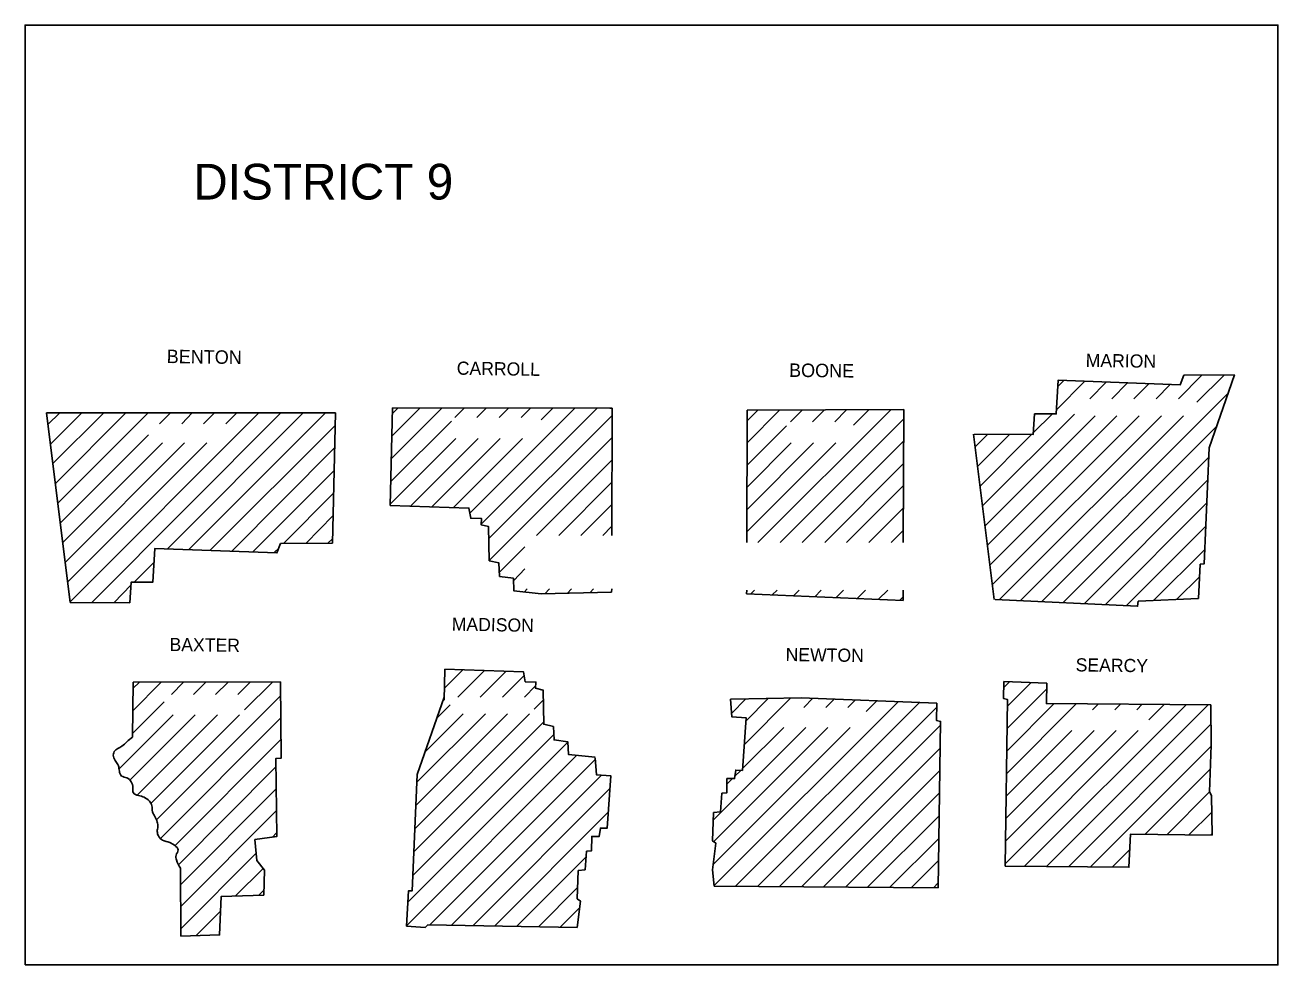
# Model space of a CAD drawing. Extents: x 76 to 6945, y -3933 to 2152.
# Drawn here: x 6134.1 to 6534.1, y -3562.5 to -3262.5 of the extents above; entities that cross this region are included whole.
import ezdxf

# ---------------------------------------------------------------- set-up
doc = ezdxf.new("R2010")
doc.units = 0
doc.layers.add('R_Draft', color=7, linetype='Continuous')

msp = doc.modelspace()

# ---------------------------------------------------------------- linework, layer by layer
at = {"layer": 'R_Draft'}
msp.add_lwpolyline([(6134.06, -3562.46), (6134.06, -3262.46), (6534.06, -3262.46), (6534.06, -3562.46)], close=True, dxfattribs=at)
for points in [[(6437.16, -3393.06), (6455.86, -3393.16), (6456.36, -3386.56), (6463.26, -3386.56), (6463.86, -3375.86), (6502.86, -3377.26), (6504.06, -3374.26), (6520.16, -3374.16), (6512.06, -3397.36), (6510.46, -3434.46), (6509.26, -3434.56), (6508.66, -3445.46)], [(6463.76, -3377.86), (6465.66, -3375.96)], [(6502.26, -3381.76), (6509.76, -3374.26)], [(6508.16, -3382.86), (6516.86, -3374.26)], [(6463.36, -3385.26), (6472.36, -3376.16)], [(6473.96, -3381.76), (6479.26, -3376.46)], [(6481.06, -3381.76), (6486.06, -3376.66)], [(6488.06, -3381.76), (6492.96, -3376.86)], [(6495.16, -3381.76), (6499.66, -3377.16)], [(6451.86, -3446.16), (6518.06, -3380.06)], [(6148.46, -3446.76), (6140.86, -3386.26)], [(6140.86, -3386.26), (6233.16, -3386.26)], [(6141.36, -3389.96), (6145.16, -3386.26)], [(6142.16, -3396.26), (6152.16, -3386.26)], [(6142.96, -3402.46), (6159.16, -3386.26)], [(6143.76, -3408.76), (6166.26, -3386.26)], [(6144.56, -3415.06), (6173.36, -3386.26)], [(6148.56, -3446.46), (6208.66, -3386.26)], [(6155.36, -3446.76), (6215.76, -3386.26)], [(6176.96, -3389.76), (6180.46, -3386.26)], [(6179.46, -3429.76), (6222.86, -3386.26)], [(6184.06, -3389.76), (6187.46, -3386.26)], [(6186.26, -3429.96), (6229.96, -3386.26)], [(6191.06, -3389.76), (6194.56, -3386.26)], [(6198.16, -3389.76), (6201.66, -3386.26)], [(6233.16, -3386.26), (6232.26, -3427.86)], [(6250.66, -3415.86), (6251.36, -3384.66)], [(6250.96, -3400.96), (6267.26, -3384.66)], [(6251.16, -3393.66), (6260.16, -3384.66)], [(6251.36, -3386.46), (6253.16, -3384.66)], [(6251.36, -3384.66), (6320.76, -3384.76), (6321.46, -3384.76)], [(6271.26, -3387.76), (6274.36, -3384.66)], [(6276.06, -3418.26), (6309.56, -3384.76)], [(6278.26, -3387.76), (6281.36, -3384.66)], [(6279.66, -3421.76), (6316.66, -3384.76)], [(6282.16, -3426.36), (6321.46, -3387.06)], [(6285.46, -3387.76), (6288.36, -3384.76)], [(6292.46, -3387.76), (6295.46, -3384.76)], [(6298.86, -3388.46), (6302.56, -3384.76)], [(6321.46, -3384.76), (6321.36, -3425.36)], [(6364.46, -3388.86), (6367.96, -3385.36)], [(6364.46, -3427.66), (6364.56, -3385.36)], [(6364.56, -3385.36), (6414.66, -3385.16)], [(6364.56, -3395.86), (6374.96, -3385.36)], [(6368.06, -3427.66), (6410.46, -3385.26)], [(6378.46, -3389.06), (6382.16, -3385.36)], [(6385.46, -3389.06), (6389.16, -3385.36)], [(6392.56, -3389.06), (6396.26, -3385.36)], [(6398.56, -3390.16), (6403.46, -3385.26)], [(6414.66, -3385.16), (6414.46, -3427.66)], [(6439.76, -3415.96), (6469.06, -3386.66)], [(6440.56, -3422.26), (6475.66, -3387.16)], [(6441.36, -3428.46), (6482.66, -3387.16)], [(6442.16, -3434.76), (6489.76, -3387.16)], [(6442.96, -3441.06), (6496.86, -3387.16)], [(6445.16, -3445.86), (6503.96, -3387.16)], [(6455.96, -3392.66), (6462.06, -3386.56)], [(6193.06, -3430.16), (6233.06, -3390.26)], [(6250.86, -3408.16), (6270.16, -3388.86)], [(6364.56, -3402.96), (6377.16, -3390.36)], [(6375.16, -3427.66), (6414.56, -3388.26)], [(6458.66, -3446.46), (6514.26, -3390.86)], [(6145.36, -3421.36), (6173.46, -3393.26)], [(6146.16, -3427.66), (6177.96, -3395.86)], [(6146.96, -3433.86), (6184.96, -3395.86)], [(6147.76, -3440.16), (6192.06, -3395.86)], [(6250.66, -3415.36), (6271.56, -3394.46)], [(6257.16, -3416.06), (6278.76, -3394.46)], [(6263.96, -3416.26), (6285.76, -3394.46)], [(6270.86, -3416.46), (6292.86, -3394.46)], [(6282.26, -3433.36), (6321.46, -3394.16)], [(6364.46, -3424.26), (6392.86, -3395.86)], [(6364.46, -3417.16), (6385.76, -3395.86)], [(6364.56, -3409.96), (6378.66, -3395.86)], [(6382.16, -3427.66), (6414.56, -3395.26)], [(6443.46, -3445.86), (6436.86, -3393.06)], [(6437.36, -3397.06), (6441.46, -3393.06)], [(6438.16, -3403.36), (6448.46, -3393.06)], [(6438.96, -3409.66), (6455.46, -3393.06)], [(6199.96, -3430.46), (6232.86, -3397.46)], [(6297.36, -3425.36), (6321.36, -3401.36)], [(6389.36, -3427.66), (6414.56, -3402.46)], [(6465.36, -3446.86), (6511.96, -3400.36)], [(6206.66, -3430.76), (6232.76, -3404.66)], [(6472.16, -3447.16), (6511.56, -3407.76)], [(6216.56, -3427.96), (6232.56, -3411.86)], [(6304.46, -3425.36), (6321.36, -3408.36)], [(6396.36, -3427.66), (6414.56, -3409.46)], [(6321.36, -3442.46), (6321.26, -3443.46), (6298.86, -3443.96), (6290.16, -3443.06), (6289.96, -3439.06), (6285.56, -3438.46), (6285.36, -3434.16), (6282.26, -3433.46), (6282.06, -3422.56), (6279.66, -3421.96), (6279.76, -3419.96), (6276.36, -3419.86), (6275.76, -3416.66), (6250.66, -3415.86)], [(6311.46, -3425.36), (6321.26, -3415.56)], [(6478.96, -3447.46), (6511.26, -3415.06)], [(6223.66, -3427.96), (6232.46, -3419.06)], [(6403.46, -3427.66), (6414.46, -3416.66)], [(6318.56, -3425.36), (6321.26, -3422.56)], [(6410.56, -3427.66), (6414.46, -3423.76)], [(6485.66, -3447.76), (6510.96, -3422.56)], [(6232.26, -3427.86), (6215.66, -3427.96), (6214.46, -3430.96), (6175.46, -3429.56), (6174.86, -3440.26), (6167.96, -3440.26), (6167.46, -3446.86), (6148.46, -3446.76)], [(6230.66, -3427.96), (6232.36, -3426.36)], [(6213.46, -3430.96), (6215.16, -3429.36)], [(6285.56, -3437.06), (6293.66, -3428.96)], [(6494.36, -3446.16), (6510.56, -3429.96)], [(6168.86, -3440.26), (6175.26, -3433.86)], [(6290.06, -3439.76), (6293.66, -3436.06)], [(6501.86, -3445.66), (6509.06, -3438.56)], [(6162.36, -3446.86), (6167.96, -3441.16)], [(6293.46, -3443.36), (6294.36, -3442.46)], [(6299.96, -3443.96), (6301.46, -3442.46)], [(6307.16, -3443.86), (6308.56, -3442.46)], [(6314.46, -3443.56), (6315.56, -3442.46)], [(6364.36, -3444.06), (6364.46, -3442.86)], [(6365.76, -3444.06), (6366.96, -3442.86)], [(6372.56, -3444.36), (6374.16, -3442.86)], [(6379.36, -3444.66), (6381.16, -3442.86)], [(6386.16, -3444.96), (6388.26, -3442.86)], [(6392.96, -3445.26), (6395.36, -3442.86)], [(6399.76, -3445.46), (6402.36, -3442.86)], [(6406.56, -3445.76), (6409.46, -3442.86)], [(6414.46, -3442.86), (6414.36, -3446.16)], [(6414.36, -3446.16), (6364.36, -3444.06)], [(6413.36, -3446.06), (6414.46, -3444.96)], [(6508.66, -3445.46), (6489.46, -3446.36), (6489.26, -3447.96), (6443.76, -3445.86)], [(6267.86, -3477.96), (6268.06, -3468.06)], [(6267.86, -3474.26), (6273.86, -3468.26)], [(6268.06, -3468.06), (6293.16, -3468.86), (6293.76, -3472.06), (6297.16, -3472.16), (6297.06, -3474.16), (6299.46, -3474.76), (6299.66, -3485.66), (6302.76, -3486.36), (6302.96, -3490.66), (6307.36, -3491.26), (6307.56, -3495.26), (6316.06, -3496.16)], [(6272.26, -3476.96), (6280.66, -3468.56)], [(6279.36, -3476.96), (6287.56, -3468.76)], [(6286.46, -3476.96), (6293.36, -3470.06)], [(6446.96, -3530.96), (6447.76, -3477.76), (6446.46, -3477.46), (6446.56, -3471.96)], [(6446.56, -3471.96), (6460.26, -3472.56), (6460.16, -3479.06), (6512.66, -3479.46)], [(6446.56, -3473.96), (6448.46, -3471.96)], [(6168.36, -3489.76), (6168.56, -3472.16)], [(6168.46, -3481.36), (6177.56, -3472.26)], [(6168.46, -3474.26), (6170.56, -3472.26)], [(6168.56, -3472.16), (6215.66, -3472.06)], [(6180.76, -3476.16), (6184.66, -3472.26)], [(6215.66, -3472.06), (6215.86, -3496.46), (6214.16, -3496.56), (6214.46, -3521.46), (6207.46, -3522.46), (6208.06, -3529.16), (6210.46, -3532.26), (6210.26, -3540.16), (6196.66, -3540.66), (6196.16, -3552.86), (6183.76, -3553.26)], [(6187.86, -3476.16), (6191.76, -3472.26)], [(6194.86, -3476.16), (6198.86, -3472.16)], [(6201.96, -3476.16), (6205.96, -3472.16)], [(6204.16, -3481.06), (6213.06, -3472.16)], [(6293.46, -3476.96), (6297.06, -3473.36)], [(6447.66, -3486.96), (6460.16, -3474.46)], [(6447.76, -3479.86), (6455.26, -3472.36)], [(6168.46, -3488.46), (6178.46, -3478.46)], [(6176.06, -3516.16), (6215.66, -3476.56)], [(6310.36, -3550.56), (6262.66, -3549.66), (6261.76, -3550.56), (6255.86, -3550.06), (6256.46, -3538.86), (6257.66, -3538.76), (6259.26, -3501.66), (6267.86, -3476.96)], [(6265.46, -3483.76), (6269.76, -3479.46)], [(6296.56, -3480.86), (6299.46, -3477.96)], [(6353.56, -3532.06), (6354.56, -3523.56), (6353.56, -3522.86), (6353.86, -3513.86), (6356.06, -3513.56), (6356.56, -3507.66), (6358.06, -3507.56), (6358.16, -3502.96), (6360.56, -3502.96), (6360.96, -3500.26), (6363.06, -3500.36), (6364.26, -3483.56), (6359.66, -3483.26), (6359.26, -3477.66)], [(6354.06, -3537.06), (6412.76, -3478.46)], [(6359.26, -3477.66), (6359.46, -3477.66), (6381.86, -3477.16)], [(6359.66, -3482.06), (6364.06, -3477.66)], [(6360.86, -3537.36), (6419.56, -3478.76)], [(6363.66, -3492.16), (6378.56, -3477.26)], [(6364.16, -3484.66), (6371.36, -3477.36)], [(6381.86, -3477.16), (6425.16, -3478.96)], [(6382.66, -3480.26), (6385.56, -3477.36)], [(6389.76, -3480.26), (6392.36, -3477.66)], [(6396.76, -3480.26), (6399.16, -3477.86)], [(6402.56, -3481.56), (6405.96, -3478.16)], [(6425.16, -3478.96), (6425.06, -3484.46), (6426.36, -3484.76), (6425.56, -3537.86)], [(6447.46, -3501.36), (6469.66, -3479.16)], [(6447.56, -3494.16), (6462.66, -3479.06)], [(6453.16, -3530.96), (6504.76, -3479.46)], [(6460.16, -3531.06), (6511.76, -3479.46)], [(6474.86, -3481.06), (6476.76, -3479.16)], [(6481.96, -3481.06), (6483.76, -3479.26)], [(6488.96, -3481.06), (6490.76, -3479.26)], [(6492.86, -3484.26), (6497.76, -3479.36)], [(6512.66, -3479.46), (6512.76, -3492.36)], [(6164.06, -3499.86), (6181.36, -3482.66)], [(6167.66, -3503.36), (6188.36, -3482.66)], [(6169.86, -3508.26), (6195.46, -3482.66)], [(6174.36, -3510.86), (6202.56, -3482.66)], [(6177.36, -3521.96), (6215.76, -3483.56)], [(6258.56, -3518.96), (6295.16, -3482.36)], [(6258.86, -3511.56), (6288.06, -3482.36)], [(6259.16, -3504.16), (6281.06, -3482.36)], [(6261.76, -3494.46), (6273.96, -3482.36)], [(6367.86, -3537.46), (6425.06, -3480.26)], [(6258.26, -3526.26), (6299.56, -3484.96)], [(6353.86, -3530.26), (6397.46, -3486.66)], [(6353.86, -3516.16), (6383.36, -3486.66)], [(6353.96, -3523.06), (6390.36, -3486.66)], [(6363.16, -3499.76), (6376.26, -3486.66)], [(6374.86, -3537.56), (6426.26, -3486.06)], [(6447.06, -3530.06), (6489.46, -3487.66)], [(6447.06, -3522.96), (6482.36, -3487.66)], [(6447.26, -3515.66), (6475.36, -3487.66)], [(6447.26, -3508.56), (6468.26, -3487.66)], [(6467.16, -3531.16), (6512.66, -3485.66)], [(6181.96, -3524.36), (6215.76, -3490.56)], [(6256.26, -3542.46), (6307.36, -3491.36)], [(6257.96, -3533.76), (6302.86, -3488.86)], [(6255.96, -3549.86), (6310.16, -3495.66)], [(6381.96, -3537.56), (6426.26, -3493.26)], [(6474.26, -3531.16), (6512.66, -3492.76)], [(6512.76, -3492.36), (6512.16, -3507.16), (6512.86, -3508.36), (6513.06, -3521.06)], [(6183.16, -3530.36), (6214.16, -3499.26)], [(6263.26, -3549.66), (6316.06, -3496.86)], [(6316.06, -3496.36), (6316.46, -3501.76), (6321.06, -3502.06), (6319.86, -3518.86), (6317.76, -3518.76), (6317.36, -3521.46), (6314.96, -3521.46), (6314.86, -3526.06), (6313.36, -3526.16), (6312.86, -3532.06), (6310.66, -3532.36), (6310.36, -3541.36), (6311.36, -3542.06), (6310.36, -3550.56)], [(6491.66, -3520.76), (6512.46, -3499.96)], [(6270.16, -3549.76), (6318.06, -3501.86)], [(6358.16, -3504.76), (6359.96, -3502.96)], [(6360.66, -3502.26), (6362.56, -3500.36)], [(6388.96, -3537.56), (6426.06, -3500.46)], [(6183.66, -3536.86), (6214.26, -3506.26)], [(6277.16, -3549.86), (6320.66, -3506.26)], [(6395.96, -3537.66), (6426.06, -3507.56)], [(6498.66, -3520.86), (6512.26, -3507.26)], [(6183.76, -3543.86), (6214.26, -3513.26)], [(6284.06, -3549.96), (6320.16, -3513.86)], [(6403.06, -3537.66), (6425.86, -3514.86)], [(6505.56, -3520.96), (6512.96, -3513.66)], [(6212.96, -3521.76), (6214.36, -3520.26)], [(6410.06, -3537.76), (6425.86, -3521.96)], [(6513.06, -3521.06), (6486.96, -3520.76), (6486.46, -3531.26), (6446.96, -3530.96)], [(6512.66, -3520.96), (6512.96, -3520.66)], [(6183.76, -3550.96), (6207.76, -3526.86)], [(6290.96, -3550.16), (6313.16, -3527.96)], [(6481.26, -3531.16), (6486.76, -3525.66)], [(6183.76, -3553.26), (6183.66, -3531.56)], [(6201.26, -3540.46), (6209.96, -3531.76)], [(6417.06, -3537.76), (6425.66, -3529.16)], [(6354.06, -3537.36), (6353.56, -3532.06)], [(6208.66, -3540.16), (6210.26, -3538.56)], [(6297.96, -3550.26), (6310.56, -3537.66)], [(6425.56, -3537.86), (6354.06, -3537.36)], [(6424.06, -3537.86), (6425.56, -3536.26)], [(6188.66, -3553.06), (6196.46, -3545.26)], [(6304.86, -3550.46), (6311.16, -3544.16)], [(6195.96, -3552.86), (6196.16, -3552.66)]]:
    msp.add_lwpolyline(points, dxfattribs=at)
msp.add_spline([(6183.66, -3531.56), (6182.36, -3528.96), (6182.26, -3527.46), (6182.96, -3525.76), (6181.86, -3524.36), (6180.26, -3523.36), (6177.96, -3522.66), (6176.66, -3521.26), (6176.26, -3519.86), (6176.46, -3518.36), (6176.26, -3516.86), (6175.46, -3515.06), (6174.76, -3513.56), (6174.56, -3511.66), (6173.76, -3510.16), (6172.06, -3508.96), (6170.26, -3508.36), (6168.66, -3507.56), (6168.46, -3505.86), (6167.96, -3504.06), (6166.56, -3502.76), (6164.86, -3502.16), (6164.16, -3500.66), (6163.86, -3498.86), (6163.06, -3497.56), (6162.26, -3495.96), (6162.56, -3494.36), (6164.96, -3492.66), (6166.56, -3491.26), (6168.36, -3489.76)], degree=3, dxfattribs=at)

# ---------------------------------------------------------------- texts
msp.add_text('DISTRICT 9', height=11.4, dxfattribs=at).set_placement((6187.76, -3318.16))
for s, height, rotation, p in [('BENTON', 4.301, 359.2527, (6179.26, -3370.36)), ('MARION', 4.201, 359.1854, (6472.66, -3371.56)), ('CARROLL', 4.201, 359.1481, (6271.86, -3374.06)), ('BOONE', 4.301, 359.4001, (6377.96, -3374.76)), ('MADISON', 4.201, 359.0906, (6270.26, -3455.76)), ('BAXTER', 4.201, 359.2559, (6180.16, -3462.26)), ('NEWTON', 4.201, 359.2717, (6376.86, -3465.46)), ('SEARCY', 4.199, 359.2527, (6469.46, -3468.76))]:
    msp.add_text(s, height=height, rotation=rotation, dxfattribs=at).set_placement(p)

doc.saveas('drawing.dxf')
